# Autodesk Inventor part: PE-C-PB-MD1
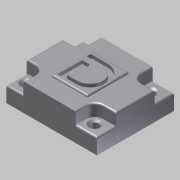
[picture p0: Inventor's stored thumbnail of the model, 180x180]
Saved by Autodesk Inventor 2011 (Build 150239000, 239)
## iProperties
Created: 2010-07
Part Number: PE-C-PB-MD1
Document SubType Name: Modeling
Designer: demin
Density: 1 g/cm^3
Author: demin
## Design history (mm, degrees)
sketch "Эскиз1"
  geometry: L1 (-26.5, 22.5)-(26.5, 22.5); L2 (26.5, 22.5)-(26.5, -22.5); L3 (26.5, -22.5)-(-26.5, -22.5); L4 (-26.5, -22.5)-(-26.5, 22.5); 3 further points
  constraints: 8 end point, 2 midpoint, 2 parallel, 1 horizontal, 1 horizontal alignment, 1 perpendicular, 1 vertical alignment
  dimensions: "d0" = 53 distance of L2.end L3.end; "d1" = 45 distance of L1.end L2.end
extrude "Выдавливание1" new body sketch "Эскиз1" distance "d2" = 17; taper "d3" = 0 deg
sketch "Эскиз2"
  geometry: L1 (26.5, 22.5)-(26.5, -22.5) reference; L2 (-26.5, 22.5)-(26.5, 22.5) reference; L3 (-26.5, -22.5)-(-26.5, 22.5) reference; L4 (26.5, -22.5)-(-26.5, -22.5) reference; L5 (-10.5, 12)-(10.5, 12); L6 (10.5, 12)-(10.5, -12); L7 (10.5, -12)-(-10.5, -12); L8 (-10.5, -12)-(-10.5, 12); 3 further points
  constraints: 8 end point, 2 midpoint, 2 parallel, 1 horizontal, 1 horizontal alignment, 1 perpendicular, 1 vertical alignment
  dimensions: "d4" = 21 distance of L6.end L7.end; "d5" = 24 distance of L5.end L6.end
extrude "Выдавливание2" cut sketch "Эскиз2" distance "d6" = 1; taper "d7" = 0 deg
sketch "Эскиз3"
  geometry: L1 (-26.5, 22.5)-(26.5, 22.5) reference; L2 (-26.5, -22.5)-(-26.5, 22.5) reference; L3 (-10.5, 12)-(-10.5, -12) reference; L4 (10.5, 12)-(-10.5, 12) reference; L5 (10.5, -12)-(10.5, 12) reference; L6 (-10.5, -12)-(10.5, -12) reference; L7 (-26.5, 22.5)-(26.5, 22.5) reference; L8 (-26.5, -22.5)-(-26.5, 22.5) reference; L9 (26.5, -22.5)-(-26.5, -22.5) reference; L10 (26.5, 22.5)-(26.5, -22.5) reference; L11 (0, 5.068)-(0, -22.5); L12 (-5.761, 0)-(14.87, 0); L13 (26.5, 22.5)-(26.5, -22.5) reference; L14 (-25.014, 15.5)-(-17.384, 15.5); L15 (-21.5, 20.01)-(-21.5, 10.907); L16 (26.5, 22.5)-(26.5, -22.5) reference; L17 (17.535, 16.25)-(20.502, 16.25); L18 (19, 20.01)-(19, 10.907); L19 (-21.5, 10.5)-(-26.5, 10.5); L20 (-16.5, 15.5)-(-16.5, 22.5); L21 (-16.5, 22.5)-(-26.5, 22.5); L22 (-26.5, 22.5)-(-26.5, 10.5); L23 (14, 22.5)-(26.5, 22.5); L24 (-26.5, -22.5)-(-26.5, -10.5); L25 (-16.5, -22.5)-(-26.5, -22.5); L26 (-16.5, -15.5)-(-16.5, -22.5); L27 (-21.5, -10.5)-(-26.5, -10.5); L28 (14, 16.25)-(14, 22.5); L29 (19, 11.25)-(26.5, 11.25); L30 (14, -22.5)-(26.5, -22.5); L31 (14, -16.25)-(14, -22.5); L32 (19, -11.25)-(26.5, -11.25); L33 (26.5, -22.5)-(26.5, -11.25); L34 (26.5, -22.5)-(-26.5, -22.5) reference; L35 (26.5, -11.25)-(26.5, -22.5); L36 (26.5, 22.5)-(26.5, 11.25); A1 r 5 centre (-21.5, 15.5) between (-21.5, 10.5) and (-16.5, 15.5); A2 r 5 centre (-21.5, -15.5) between (-16.5, -15.5) and (-21.5, -10.5); A3 r 5 centre (19, 16.25) between (14, 16.25) and (19, 11.25); A4 r 5 centre (19, -16.25) between (19, -11.25) and (14, -16.25); 7 further points
  constraints: 46 end point, 16 symmetric about line, 11 point on line, 10 perpendicular, 8 point on circle, 4 centre point, 4 tangent, 3 collinear, 3 midpoint, 2 coincident, 2 other
  dimensions: "d8" = 15.5 distance from line of L12.start L14; "d9" = 21.5 distance from line of L11.start L15; "d20" = 0.75 distance from line of L17 L14.end; "d21" = 40.5 distance between parallel lines of L18 L15; "d32" = 10 diameter of A1; "d33" = 10 diameter of A3
  node "Спроецированная петля1"
hole "Отверстие1" sketch "Эскиз3" diameter "d10" = 5; stored, may be unused: countersink angle "d14" = 90 deg, drill point angle "d16" = 118 deg; dims "d11" = 6, "d12" = 6, "d13" = 2, "d15" = 8
pattern_linear "Прямоуг.массив1" dims "d19" = 31
hole "Отверстие2" sketch "Эскиз3" diameter "d22" = 5; stored, may be unused: countersink angle "d26" = 90 deg, drill point angle "d28" = 118 deg; dims "d23" = 6, "d24" = 6, "d25" = 2, "d27" = 8
pattern_linear "Прямоуг.массив2" dims "d31" = 32.5
extrude "Выдавливание3" cut sketch "Эскиз3" distance "d34" = 7; taper "d35" = 0 deg
sketch "Эскиз5"
  geometry: L1 (26.5, 22.5)-(26.5, -22.5) reference; L2 (-16.5, 22.5)-(26.5, 22.5) reference; L3 (14, 16.25)-(14, 22.5) reference; L4 (19, 11.25)-(26.5, 11.25) reference; C1 r 2.5 at (19, 16.25) reference; A1 r 5 centre (19, 16.25) between (14, 16.25) and (19, 11.25) reference; 1 further point
extrude "Выдавливание4" cut sketch "Эскиз5" distance "d36" = 7; taper "d37" = 0 deg
sketch "Эскиз6"
  geometry: L1 (-26.5, -22.5)-(-26.5, 10.5) reference; L2 (26.5, -22.5)-(-26.5, -22.5) reference; L3 (26.5, 11.25)-(26.5, -22.5) reference; L4 (14, -16.25)-(14, -22.5) reference; L5 (19, -11.25)-(26.5, -11.25) reference; L6 (-16.5, -15.5)-(-16.5, -22.5) reference; L7 (-21.5, -10.5)-(-26.5, -10.5) reference; C1 r 2.5 at (-21.5, -15.5) reference; C2 r 2.5 at (19, -16.25) reference; A1 r 5 centre (19, -16.25) between (19, -11.25) and (14, -16.25) reference; A2 r 5 centre (-21.5, -15.5) between (-16.5, -15.5) and (-21.5, -10.5) reference; 1 further point
extrude "Выдавливание5" cut sketch "Эскиз6" distance "d38" = 7; taper "d39" = 0 deg
node "РабПлоскость1"
sketch "Эскиз7"
  geometry: L1 (15.006, 0)-(-13.62, 0); L2 (0, 7.5)-(-8.74, 7.5); L3 (0, 10)-(-8.74, 10); L4 (0, -10)-(-9.126, -10); L5 (-9.126, -10)-(-9.126, 4.414); L6 (-9.126, 4.414)-(-4.953, 4.414); L7 (-4.953, 4.414)-(-4.077, 3.602); L8 (-4.077, 3.602)-(-6.127, -7.5); L9 (-6.127, -7.5)-(0, -7.5); A1 r 10 centre (0, 0) between (0, -10) and (0, 10); A2 r 7.5 centre (0, 0) between (0, -7.5) and (0, 7.5); A3 r 1.25 centre (-8.74, 8.75) between (-8.74, 10) and (-8.74, 7.5); 1 further point
  constraints: 18 end point, 6 point on circle, 4 tangent, 3 centre point, 2 coincident, 2 parallel, 1 perpendicular
  dimensions: "d41" = 20 diameter of A1; "d42" = 15 diameter of A2
feature "Рельеф1" sketch "Эскиз7" dims "d0" = 53, "d1" = 45, "d43" = 2, "d44" = 0
fillet "Сопряжение1" dims "d45" = 1
chamfer "Фаска1" distance "d47" = 1; stored, may be unused: second distance "d48" = 2, angle "d49" = 45 deg
node "Твердое тело1"
other parameters: "d40" = 5
